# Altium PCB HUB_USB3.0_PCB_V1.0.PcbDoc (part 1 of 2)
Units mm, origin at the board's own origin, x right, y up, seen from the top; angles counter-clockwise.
Board outline 100 x 80 mm, 2 copper layers (Top Layer, Bottom Layer), stack 1.071 mm thick; 154 components, 104 nets, 521 pads, 700 vias.
Unrouted connection lines stored in the file: 114.
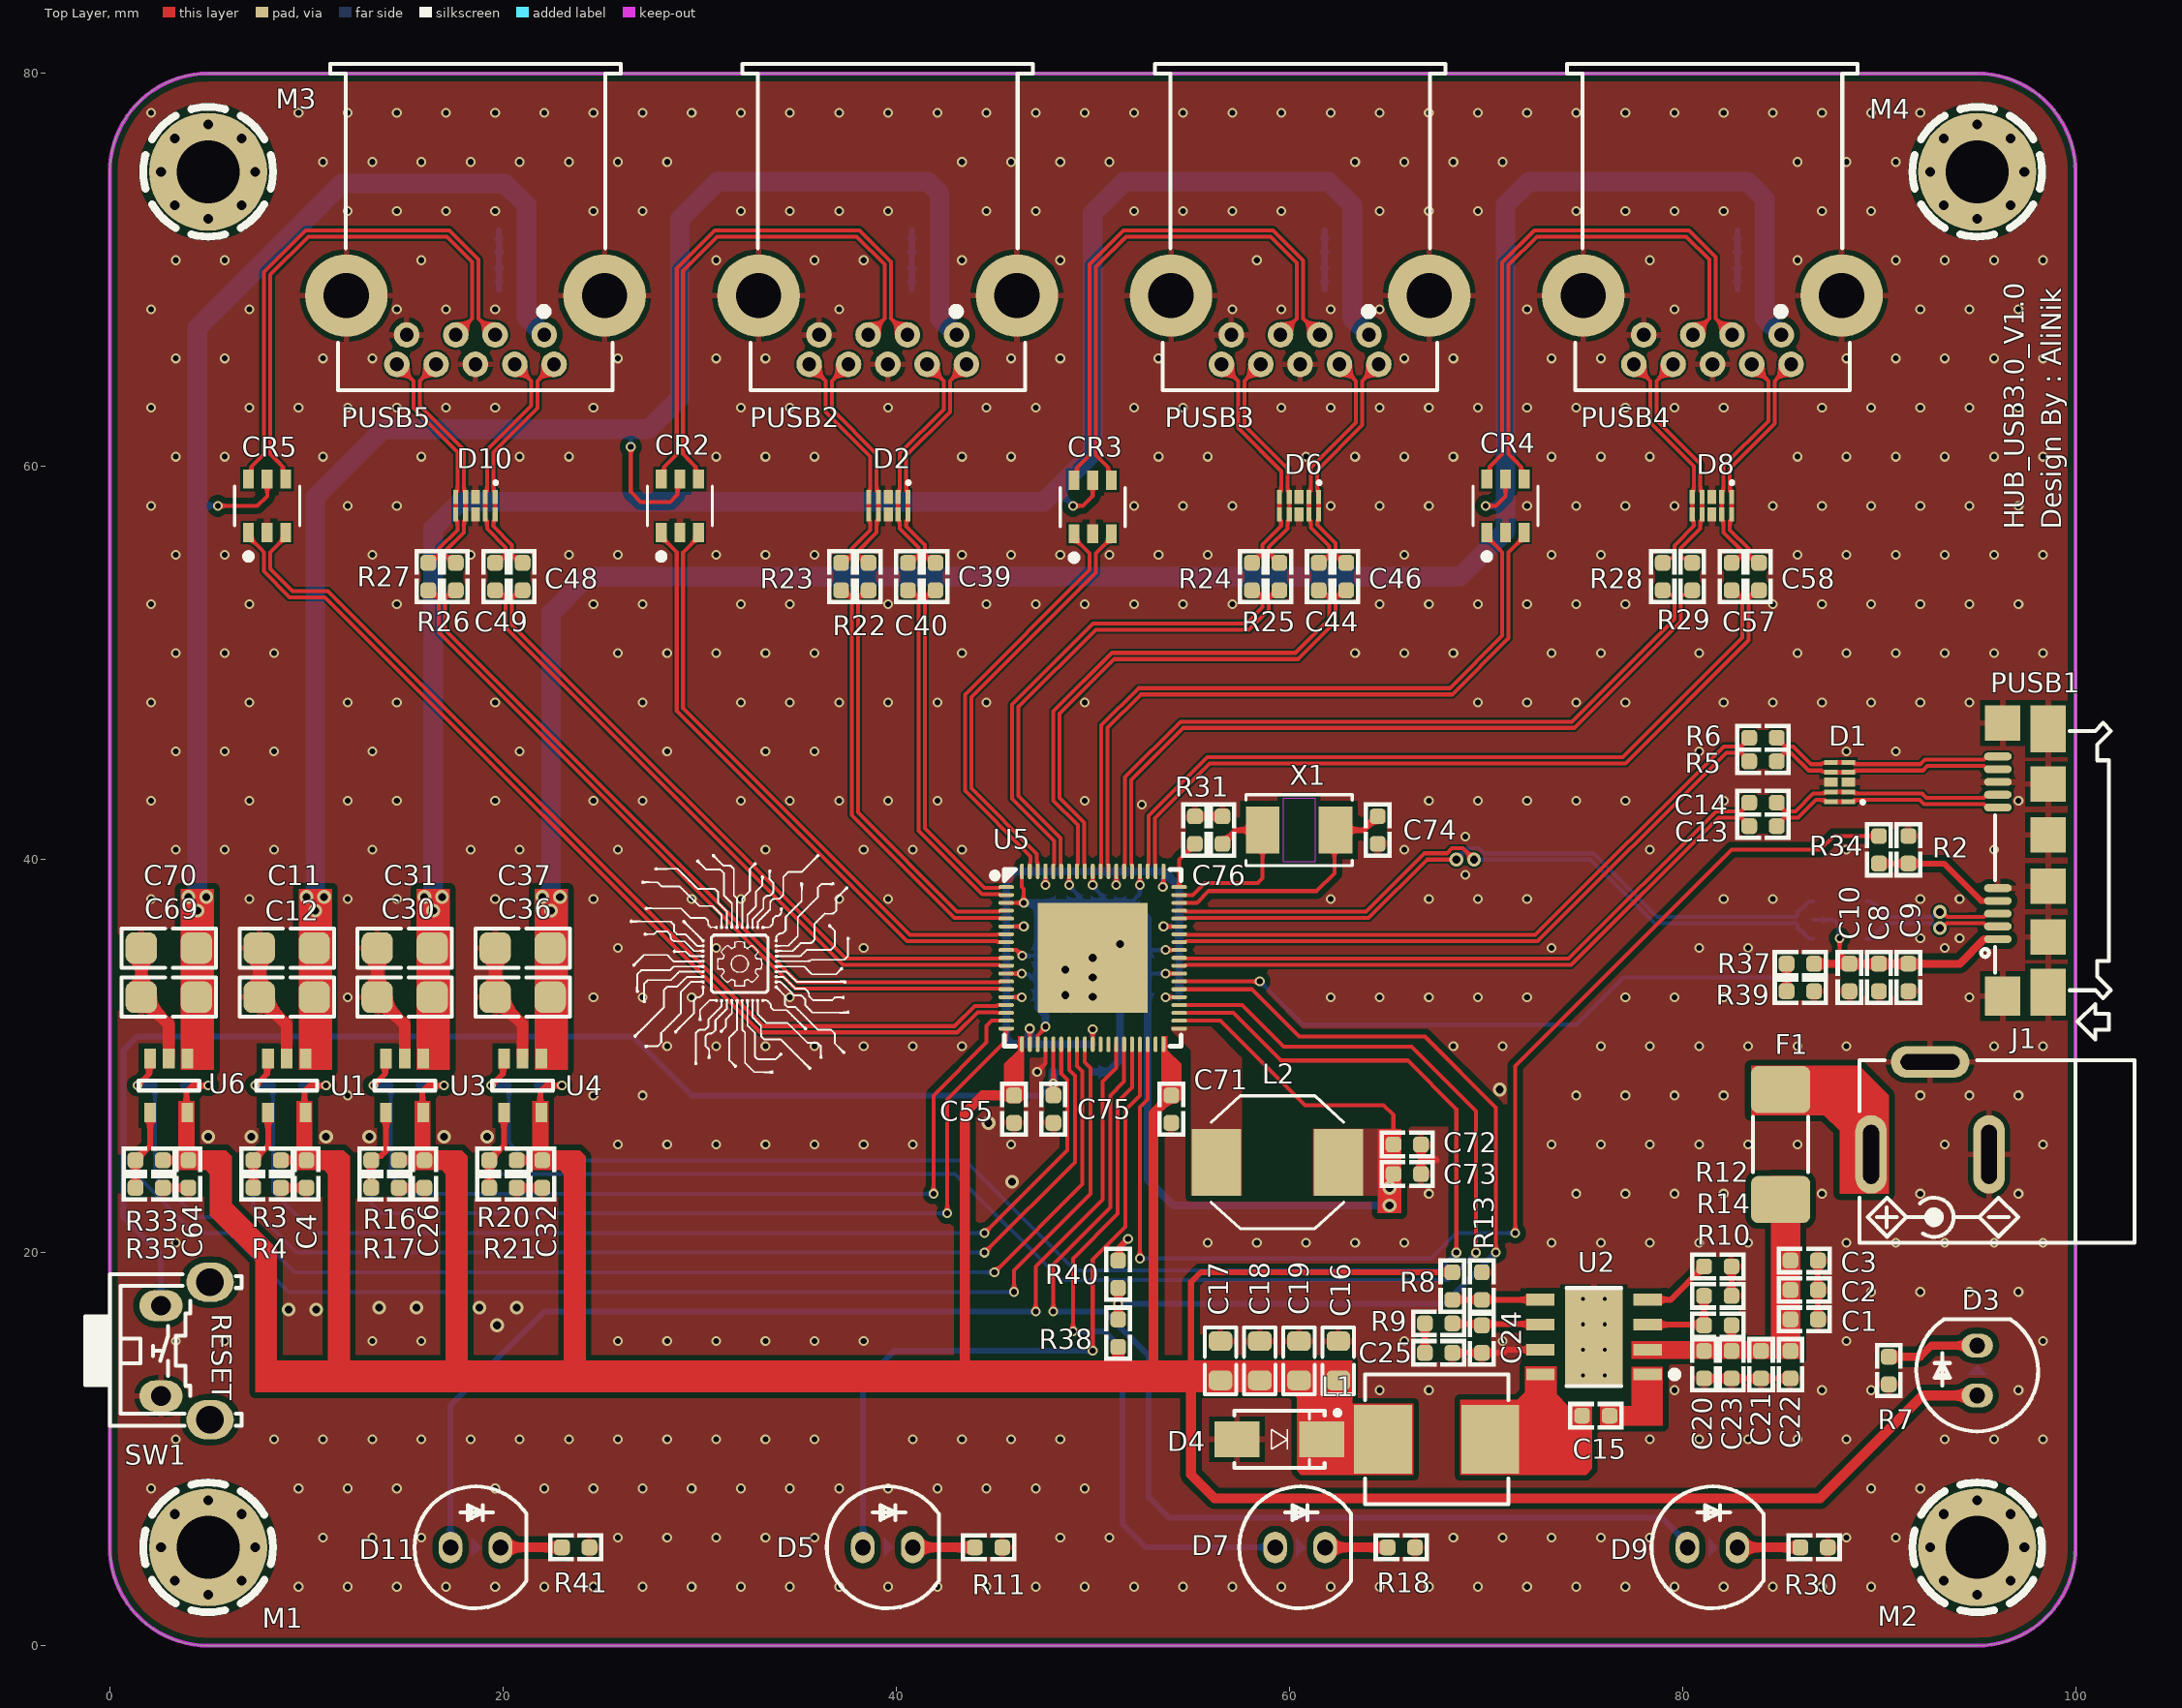
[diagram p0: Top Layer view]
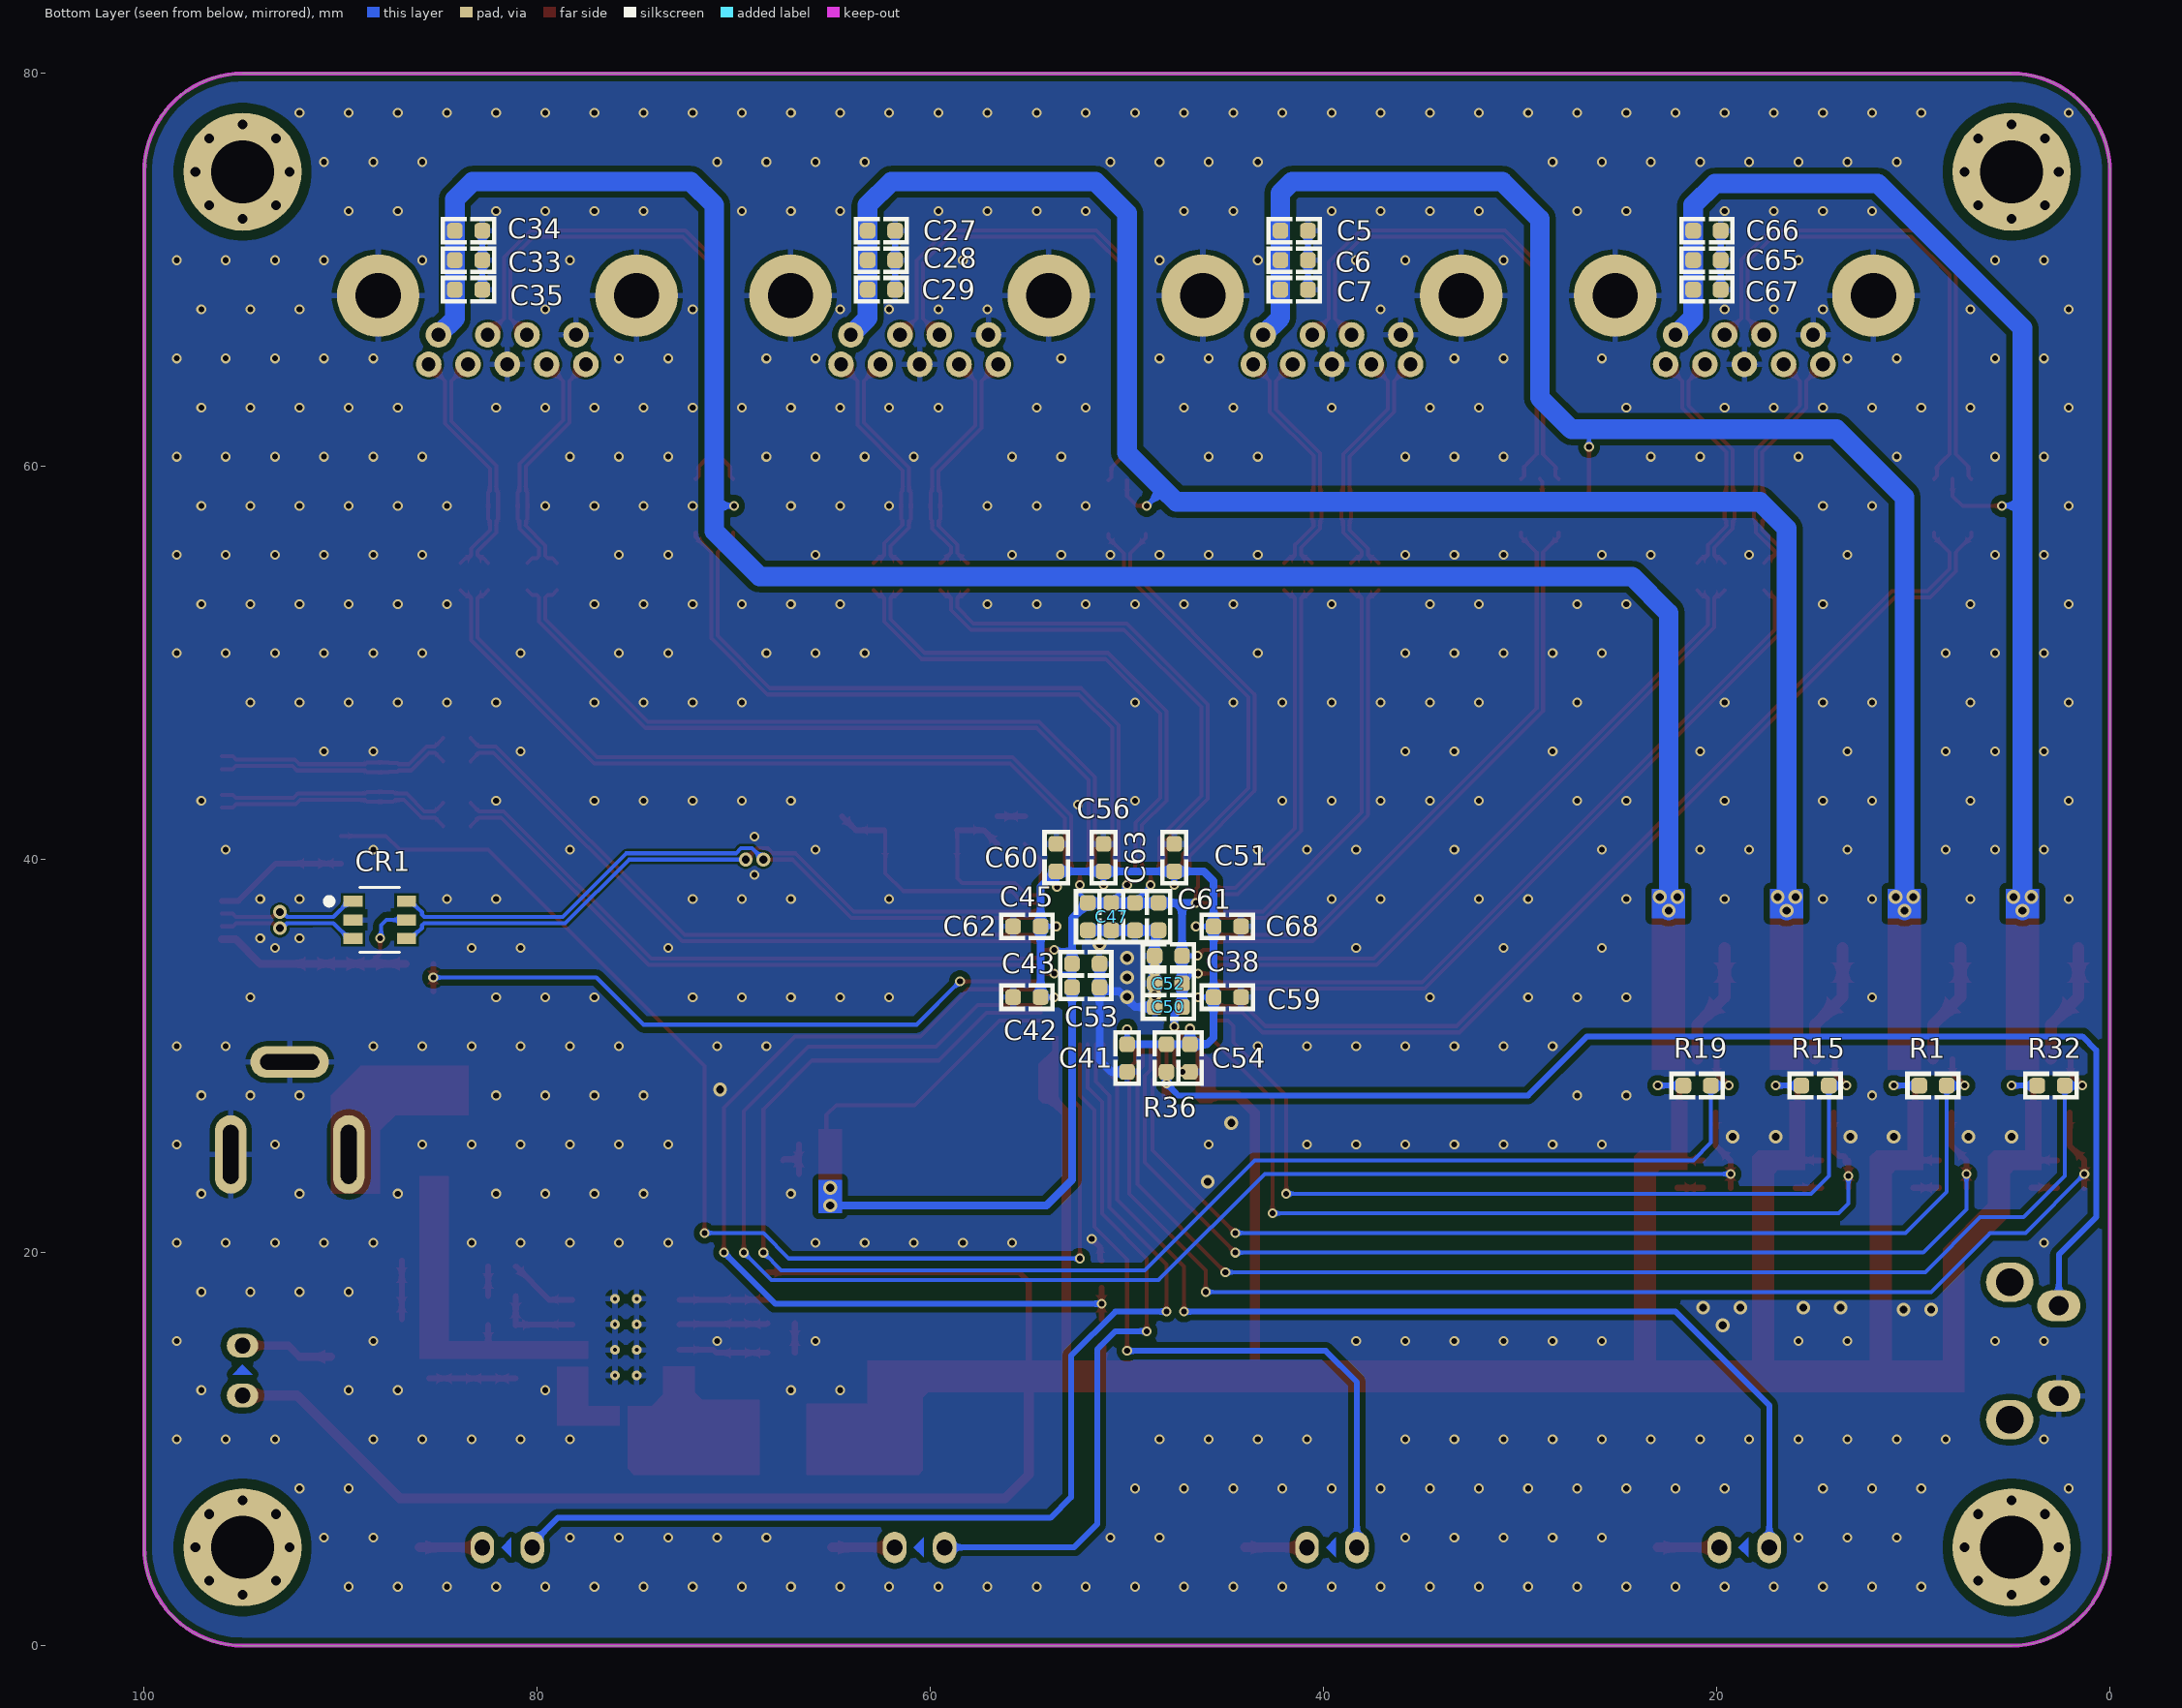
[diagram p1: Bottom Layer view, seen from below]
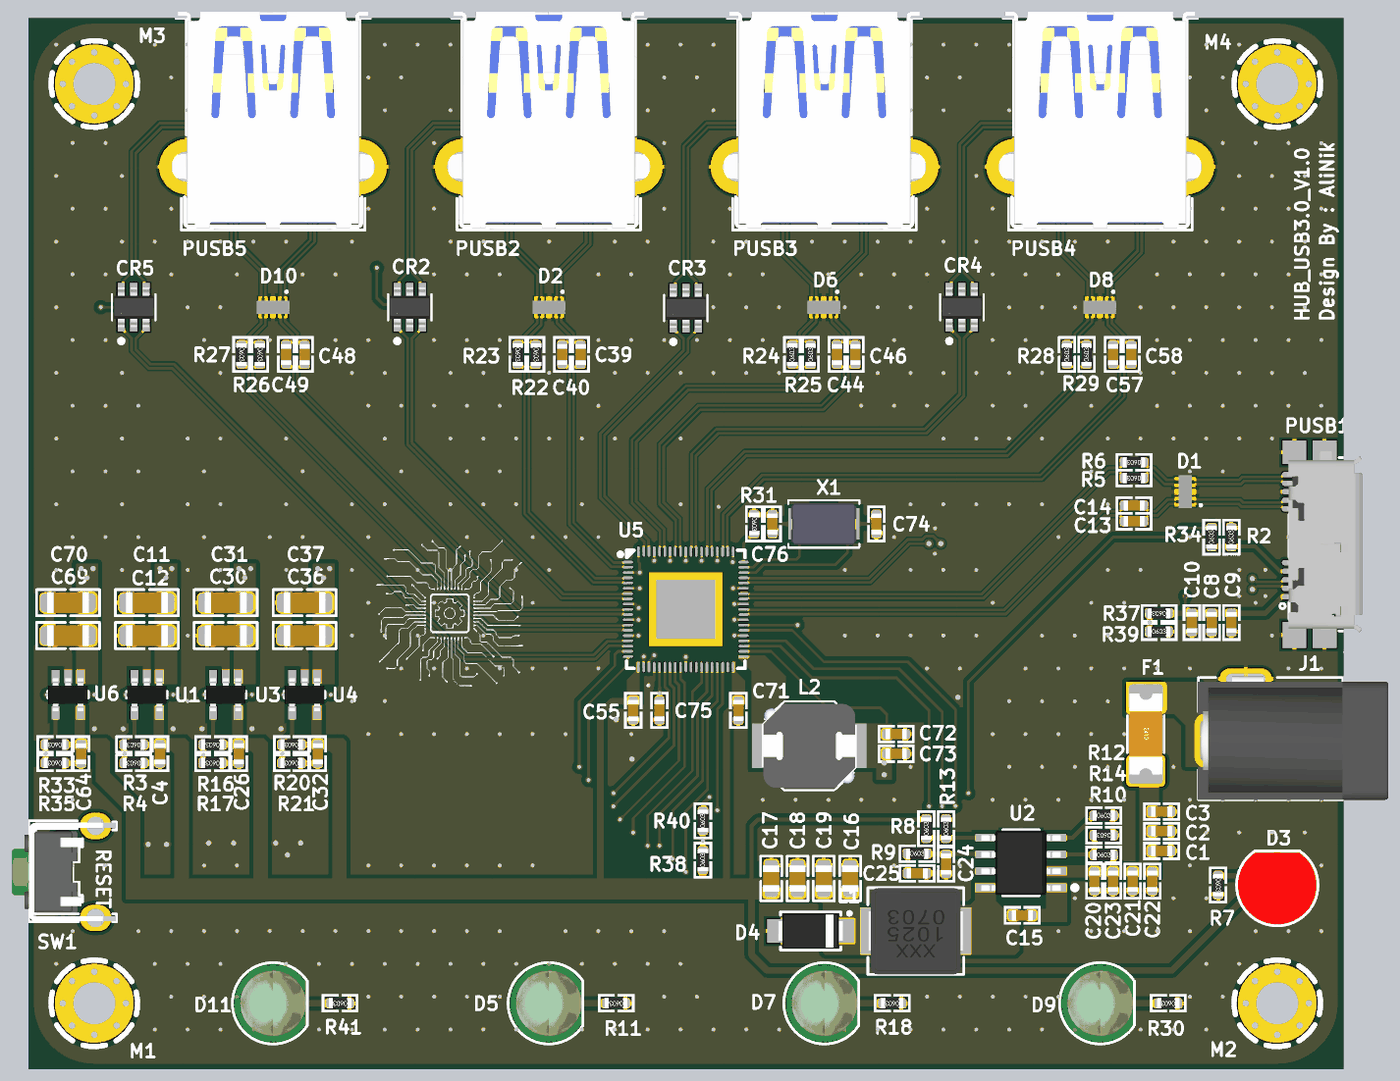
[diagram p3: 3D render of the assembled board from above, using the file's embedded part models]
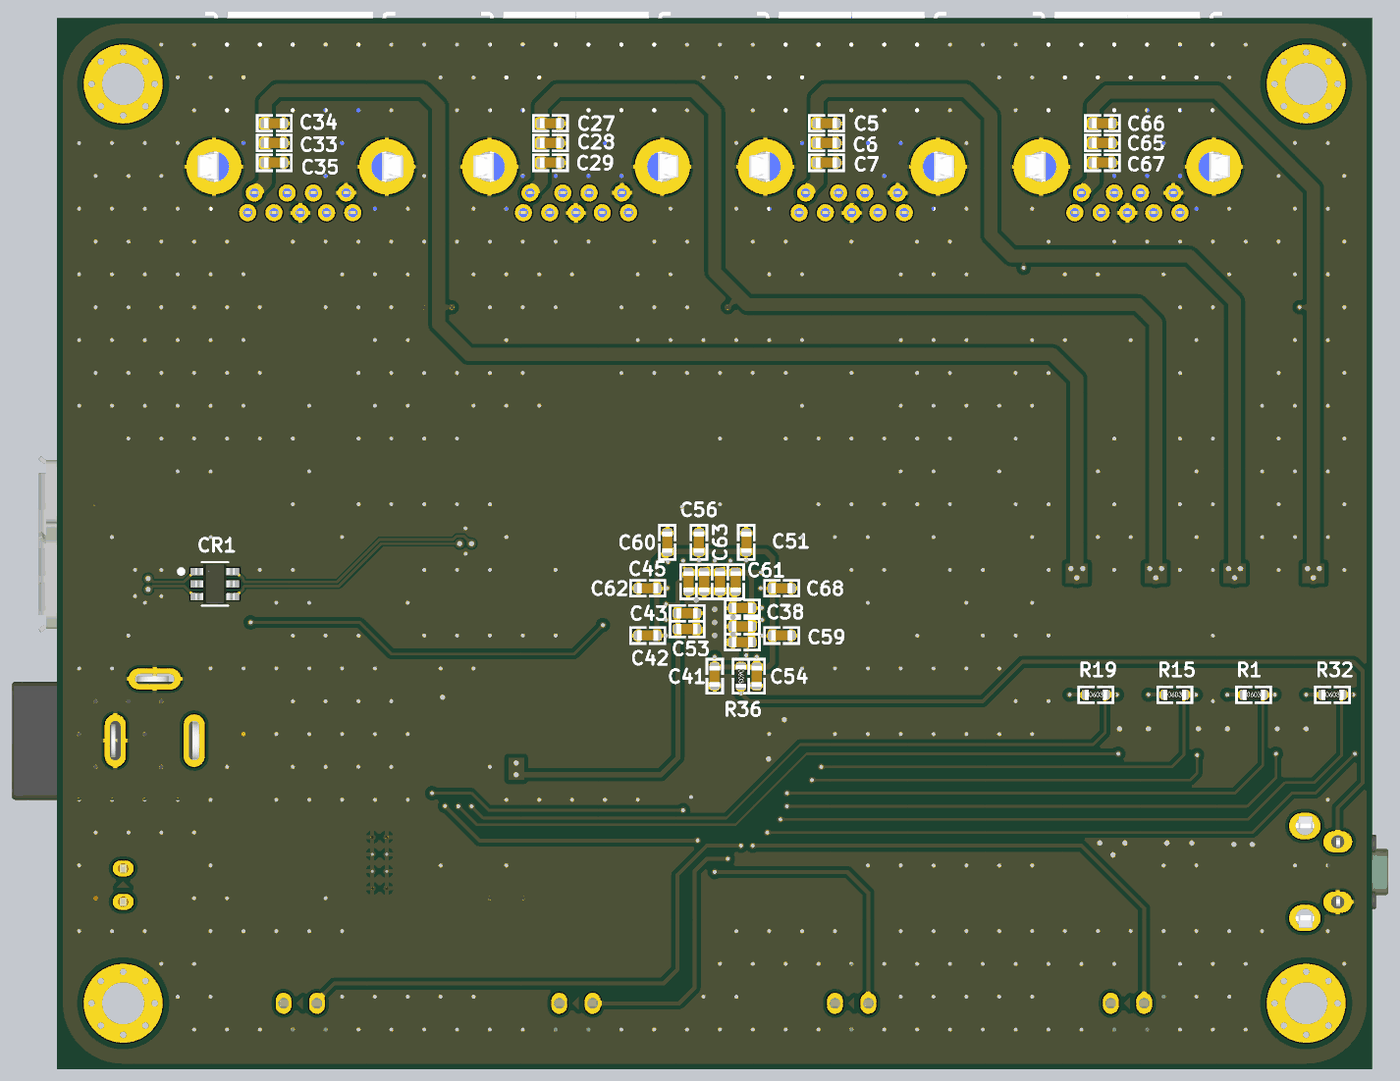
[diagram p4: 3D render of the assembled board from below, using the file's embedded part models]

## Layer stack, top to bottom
Top Solder: solder mask 0.0102, Solder Resist, Dk 3.5
Top Layer: signal copper 0.0356
Dielectric 1: dielectric 1, FR-4, Dk 4.8
Bottom Layer: signal copper 0.0356
Bottom Solder: solder mask 0.0102, Solder Resist, Dk 3.5

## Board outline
0,5 0,75 cw(c5,75) 5,80 95,80 cw(c95,75) 100,75 100,5 cw(c95,5) 95,0 5,0 cw(c5,5)

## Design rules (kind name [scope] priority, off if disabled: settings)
Clearance Clearance_USB [InNetClass('USB2.0') or InNetClass('USB3.0') vs InNetClass('USB2.0') or InNetClass('USB3.0') or InNet('GND')] p1: gap=0.12 ignorepadtopadclearanceinfootprint=FALSE
Clearance Clearance_Polygon [InPolygon and InNet('GND')] p2: gap=0.3 ignorepadtopadclearanceinfootprint=TRUE
Clearance [All] p3: gap=0.18 ignorepadtopadclearanceinfootprint=TRUE
DiffPairsRouting [All] p1: maxlimit=0.12 minlimit=0.12 mostfreqgap=0.12 toplayer_minwidth=0.2 toplayer_maxwidth=0.2 toplayer_prefwidth=0.2 bottomlayer_minwidth=0.2 bottomlayer_maxwidth=0.2 bottomlayer_prefwidth=0.2 impedanceprofiledriven=TRUE impedanceprofileid={F587BD4B-BCB3-41A8-9E42-C4C83C8BF323} impedanceprofilevalue=90.000000 maxuncoupledlength=12.7
HoleSize [All] p1: absolutevalues=TRUE maxlimit=5 minlimit=0.025 maxpercent=80.000 minpercent=20.000
MinimumSolderMaskSliver [All] p1: minsoldermaskwidth=0.15
PolygonConnect PolygonConnect_GND [InNet('GND')] p1: thpad.connectstyle=Relief thpad.reliefconductorwidth=0.3 thpad.reliefentries=4 thpad.polygonreliefangle="90 Angle" thpad.airgapwidth=0.25 smdpad.connectstyle=Relief smdpad.reliefconductorwidth=0.3 smdpad.reliefentries=4 smdpad.polygonreliefangle="90 Angle" smdpad.airgapwidth=0.25 via.connectstyle=Direct via.reliefconductorwidth=0.254 via.reliefentries=4 via.polygonreliefangle="90 Angle" via.airgapwidth=0.254
PolygonConnect [All] p2: connectstyle=Direct reliefconductorwidth=0.254 reliefentries=4 polygonreliefangle="90 Angle" airgapwidth=0.254
RoutingVias [All] p1: holewidth=0.3 width=0.5 viastyle="Through Hole" minholewidth=0.3 minwidth=0.5 maxholewidth=0.7 maxwidth=1.2
SilkToSilkClearance [All] p1: silktosilkclearance=0.15
SilkToSolderMaskClearance [IsPad] p1: minsilkscreentomaskgap=0.15 clearancetoexposedcopper=TRUE
SolderMaskExpansion [All] p1: expansion=0.102 istentingtop=FALSE
SupplyNets "Schematic Supply Nets_2" [InNet('VIN')] p1: voltage=0.000
SupplyNets "Schematic Supply Nets_11" [InNet('3.3V')] p2: voltage=0.000
SupplyNets "Schematic Supply Nets_10" [InNet('VBUS_Port4')] p3: voltage=0.000
SupplyNets "Schematic Supply Nets_9" [InNet('1.1V')] p4: voltage=0.000
SupplyNets "Schematic Supply Nets_8" [InNet('VBUS_Port2')] p5: voltage=0.000
SupplyNets "Schematic Supply Nets_6" [InNet('VBUS_Port1')] p6: voltage=0.000
SupplyNets "Schematic Supply Nets_5" [InNet('VBUS_Port3')] p7: voltage=0.000
SupplyNets "Schematic Supply Nets_4" [InNet('VBUS')] p8: voltage=0.000
SupplyNets "Schematic Supply Nets_3" [InNet('GND')] p9: voltage=0.000
SupplyNets "Schematic Supply Nets_1" [InNet('VCC')] p10: voltage=0.000
SupplyNets "Schematic Supply Nets" [InNet('5V')] p11: voltage=0.000
Width [All] p1: maxlimit=5 minlimit=0.15 preferedwidth=0.254
25 further rules are at their usual default settings.

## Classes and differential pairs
net class USB3.0: MAIN_SSRX_N MAIN_SSRX_P MAIN_SSTX_N MAIN_SSTX_P RX0_N RX0_P RX1_N RX1_P RX2_N RX2_P RX3_N RX3_P RX4_N RX4_P SSRX1_N SSRX1_P SSRX2_N SSRX2_P SSRX3_N SSRX3_P SSRX4_N SSRX4_P SSTX1_N SSTX1_P SSTX2_N SSTX2_P SSTX3_N SSTX3_P SSTX4_N SSTX4_P TX0_N TX0_P TX1_N TX1_P TX2_N TX2_P TX3_N TX3_P TX4_N TX4_P
net class USB2.0: D0_N D0_P D1_N D1_P D2_N D2_P D3_N D3_P D4_N D4_P HSD1_N HSD1_P HSD2_N HSD2_P HSD3_N HSD3_P HSD4_N HSD4_P MAIN_D_N MAIN_D_P
differential pair D0: +MAIN_D_P -MAIN_D_N
differential pair TX4: +TX4_P -TX4_N
differential pair TX3: +TX3_P -TX3_N
differential pair TX2: +TX2_P -TX2_N
differential pair TX1: +TX1_P -TX1_N
differential pair TX0: +TX0_P -TX0_N
differential pair SSTX4: +SSTX4_P -SSTX4_N
differential pair SSTX3: +SSTX3_P -SSTX3_N
differential pair SSTX2: +SSTX2_P -SSTX2_N
differential pair SSTX1: +SSTX1_P -SSTX1_N
differential pair SSRX4: +SSRX4_P -SSRX4_N
differential pair SSRX3: +SSRX3_P -SSRX3_N
differential pair SSRX2: +SSRX2_P -SSRX2_N
differential pair SSRX1: +SSRX1_P -SSRX1_N
differential pair RX4: +RX4_P -RX4_N
differential pair RX3: +RX3_P -RX3_N
differential pair RX2: +RX2_P -RX2_N
differential pair RX1: +RX1_P -RX1_N
differential pair RX0: +RX0_P -RX0_N
differential pair HSD4: +HSD4_P -HSD4_N
differential pair HSD3: +HSD3_P -HSD3_N
differential pair HSD2: +HSD2_P -HSD2_N
differential pair HSD1: +HSD1_P -HSD1_N
differential pair D4: +D4_P -D4_N
differential pair D3: +D3_P -D3_N
differential pair D2: +D2_P -D2_N
differential pair D1: +D1_P -D1_N
differential pair MAIN_SSTX: +MAIN_SSTX_P -MAIN_SSTX_N
differential pair MAIN_SSRX: +MAIN_SSRX_P -MAIN_SSRX_N
differential pair MAIN_D: +D0_P -D0_N

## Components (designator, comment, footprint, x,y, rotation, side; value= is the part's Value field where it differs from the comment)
C1 "10uF" C0603 86.2,16.6 r0 top
C2 "10uF" C0603 86.2,18.1 r0 top
C3 "100nF" C0603 86.2,19.6 r0 top
C4 "100nF" C0603 10,24 r90 top
C5 "10uF" C0603 41.5,72 r180 bottom
C6 "10uF" C0603 41.5,70.5 r180 bottom
C7 "100nF" C0603 41.5,69 r180 bottom
C8 "10uF" C0603 90,34 r270 top
C9 "10uF" C0603 91.5,34 r270 top
C10 "100nF" C0603 88.5,34 r270 top
C11 "100uF" C1206 9,35.5 r0 top
C12 "100uF" C1206 9,33 r0 top
C13 "100nF" C0603 84.1,41.7 r180 top
C14 "100nF" C0603 84.1,42.9 r180 top
C15 "100nF" C0603 75.6,11.7 r0 top
C16 "47uF" C0805 62.5,14.5 r270 top
C17 "47uF" C0805 56.5,14.5 r270 top
C18 "47uF" C0805 58.5,14.5 r270 top
C19 "47uF" C0805 60.5,14.5 r270 top
C20 "2.2uF" C0603 81.1,14.3 r90 top
C21 "2.2uF" C0603 84,14.3 r90 top
C22 "2.2uF" C0603 85.5,14.3 r90 top
C23 "2.2uF" C0603 82.5,14.3 r90 top
C24 "47pF" C0603 69.8,15.6 r270 top
C25 "4.7nF" C0603 67.6,14.9 r0 top
C26 "100nF" C0603 16,24 r90 top
C27 "10uF" C0603 62.5,72 r180 bottom
C28 "10uF" C0603 62.5,70.5 r180 bottom
C29 "100nF" C0603 62.5,69 r180 bottom
C30 "100uF" C1206 15,33 r0 top
C31 "100uF" C1206 15,35.5 r0 top
C32 "100nF" C0603 22,24 r90 top
C33 "10uF" C0603 83.5,70.5 r180 bottom
C34 "10uF" C0603 83.5,72 r180 bottom
C35 "100nF" C0603 83.5,69 r180 bottom
C36 "100uF" C1206 21,33 r0 top
C37 "100uF" C1206 21,35.5 r0 top
C38 "100nF" C0603 47.9,35.1 r180 bottom
C39 "100nF" C0603 42,54.4 r270 top
C40 "100nF" C0603 40.6,54.4 r270 top
C41 "100nF" C0603 50,29.9 r90 bottom
C42 "100nF" C0603 55.1,33 r180 bottom
C43 "100nF" C0603 52.1,34.7 r0 bottom
C44 "100nF" C0603 61.5,54.4 r90 top
C45 "100nF" C0603 52,37.1 r90 bottom
C46 "100nF" C0603 62.9,54.4 r90 top
C47 "100nF" C0603 50.8,37.1 r90 bottom
C48 "100nF" C0603 21,54.4 r270 top
C49 "100nF" C0603 19.6,54.4 r270 top
C50 "100nF" C0603 47.9,32.5 r180 bottom
C51 "100nF" C0603 47.6,40.1 r270 bottom
C52 "100nF" C0603 47.9,33.7 r180 bottom
C53 "100nF" C0603 52.1,33.5 r0 bottom
C54 "4.7uF" C0603 46.8,29.9 r90 bottom
C55 "10uF" C0603 46,27.3 r90 top
C56 "100nF" C0603 51.2,40.1 r270 bottom
C57 "100nF" C0603 82.5,54.4 r90 top
C58 "100nF" C0603 83.9,54.4 r90 top
C59 "100nF" C0603 44.9,33 r0 bottom
C60 "100nF" C0603 53.6,40.1 r270 bottom
C61 "100nF" C0603 48.4,37.1 r90 bottom
C62 "100nF" C0603 55.1,36.6 r180 bottom
C63 "100nF" C0603 49.6,37.1 r90 bottom
C64 "100nF" C0603 4,24 r90 top
C65 "10uF" C0603 20.5,70.5 r180 bottom
C66 "10uF" C0603 20.5,72 r180 bottom
C67 "100nF" C0603 20.5,69 r180 bottom
C68 "100nF" C0603 44.9,36.6 r0 bottom
C69 "100uF" C1206 3,33 r0 top
C70 "100uF" C1206 3,35.5 r0 top
C71 "10uF" C0603 54,27.3 r270 top
C72 "10uF" C0603 66,25.5 r0 top
C73 "10uF" C0603 66,24 r0 top
C74 "15pF" C0603 64.5,41.5 r270 top
C75 "100nF" C0603 48,27.3 r90 top
C76 "15pF" C0603 56.6,41.5 r90 top
CR1 "USBLC6-4SC6" SOT23-6L_STM 88.018,36.928 r180 bottom
CR2 "USBLC6-4SC6" SOT23-6L_STM 29,58 r90 top
CR3 "USBLC6-4SC6" SOT23-6L_STM 50,57.938 r90 top
CR4 "USBLC6-4SC6" SOT23-6L_STM 71,58 r90 top
CR5 "USBLC6-4SC6" SOT23-6L_STM 8,58 r90 top
D1 "SEUC10F5V4U-MS" UDFN10_DTS 88,43.943 r180 top
D2 "SEUC10F5V4U-MS" UDFN10_DTS 39.6,58 r270 top
D3 "LED5MM_RED" LED5MM_RED 95,14 r90 top
D4 "SS56" DO-214AC 59.5,10.5 r0 top
D5 "LED5MM_GRN" LED5MM_GRN 39.577,5 r0 top
D6 "SEUC10F5V4U-MS" UDFN10_DTS 60.5,58 r270 top
D7 "LED5MM_GRN" LED5MM_GRN 60.553,5 r0 top
D8 "SEUC10F5V4U-MS" UDFN10_DTS 81.5,58 r270 top
D9 "LED5MM_GRN" LED5MM_GRN 81.53,5 r0 top
D10 "SEUC10F5V4U-MS" UDFN10_DTS 18.6,58 r270 top
D11 "LED5MM_GRN" LED5MM_GRN 18.6,5 r0 top
F1 "FUSE2A" F2410 85,25.5 r270 top
J1 "DC_POWER_JACK" JAC_PWR2 89.6,25 r270 top
L1 "TMPC0603H-8R2MG-D" IND_7.3x6.6mm 67.5,10.5 r180 top value=8.2uH
L2 "SPM6530T-4R7M" IND_SPM6530_TDK 59.4,24.6 r0 top value=4.7uH
M1 "DNP/MH" SCMH_M3 5,5 r0 top
M2 "DNP/MH" SCMH_M3 95,5 r0 top
M3 "DNP/MH" SCMH_M3 5,75 r0 top
M4 "DNP/MH" SCMH_M3 95,75 r0 top
PUSB1 "CONN_USB3" USB3_MICRO_B 97.2,40 r270 top
PUSB2 "CONN_USB3_A" USB3_A_RA 39.577,68.7 r0 top
PUSB3 "CONN_USB3_A" USB3_A_RA 60.553,68.7 r0 top
PUSB4 "CONN_USB3_A" USB3_A_RA 81.53,68.7 r0 top
PUSB5 "CONN_USB3_A" USB3_A_RA 18.6,68.7 r0 top
R1 "10K" R0603 9,28.5 r180 bottom
R2 "5.1K" R0603 91.5,40.5 r90 top
R3 "NA" R0603 8,24.7 r180 top
R4 "NA" R0603 8,23.3 r180 top
R5 "0R" R0603 84.1,45 r180 top
R6 "0R" R0603 84.1,46.2 r180 top
R7 "3.3K" R0603 90.5,14 r270 top
R8 "56K" R0603 68.3,18.3 r90 top
R9 "16.9K" R0603 67.6,16.4 r0 top
R10 "12K" R0603 81.8,16.3 r0 top
R11 "2.2K" R0603 44.7,5 r180 top
R12 "243K" R0603 81.8,19.3 r0 top
R13 "10K" R0603 69.8,18.3 r90 top
R14 "68K" R0603 81.8,17.8 r180 top
R15 "10K" R0603 15,28.5 r180 bottom
R16 "NA" R0603 14,24.7 r180 top
R17 "NA" R0603 14,23.3 r180 top
R18 "2.2K" R0603 65.7,5 r180 top
R19 "10K" R0603 21,28.5 r180 bottom
R20 "NA" R0603 20,24.7 r180 top
R21 "NA" R0603 20,23.3 r180 top
R22 "0R" R0603 38.6,54.4 r270 top
R23 "0R" R0603 37.2,54.4 r270 top
R24 "0R" R0603 58.1,54.4 r90 top
R25 "0R" R0603 59.5,54.4 r90 top
R26 "0R" R0603 17.6,54.4 r270 top
R27 "0R" R0603 16.2,54.4 r270 top
R28 "0R" R0603 79,54.4 r90 top
R29 "0R" R0603 80.5,54.4 r90 top
R30 "2.2K" R0603 86.7,5 r180 top
R31 "6.04K" R0603 55.2,41.5 r270 top
R32 "10K" R0603 3,28.5 r180 bottom
R33 "NA" R0603 2,24.7 r180 top
R34 "NA" R0603 90,40.5 r90 top
R35 "NA" R0603 2,23.3 r180 top
R36 "10K" R0603 48,29.9 r270 bottom
R37 "4.7K" R0603 86,34.7 r180 top
R38 "4.7K" R0603 51.3,15.9 r90 top
R39 "10K" R0603 86,33.3 r0 top
R40 "10K" R0603 51.3,18.9 r90 top
R41 "2.2K" R0603 23.7,5 r180 top
SW1 "PUSHBUTTON" SWPBT_SPST_R_6X6X4 2.6,15 r90 top
U1 "TPS2065DDBVR" DBV0005A_N 9,28.5 r270 top
U2 "TPS54560DDA" DDA0008E_N 75.5,15.7 r180 top
U3 "TPS2065DDBVR" DBV0005A_N 15,28.5 r270 top
U4 "TPS2065DDBVR" DBV0005A_N 21,28.5 r270 top
U5 "VL817-Q7(B0)" QFN-76_L9.0-W9.0-P0.40-BL-EP 50,35 r270 top
U6 "TPS2065DDBVR" DBV0005A_N 3,28.5 r270 top
X1 "7A-25.000MAAJ-T" CRYSTAL_TXC_7A_TXC 60.5,41.5 r0 top

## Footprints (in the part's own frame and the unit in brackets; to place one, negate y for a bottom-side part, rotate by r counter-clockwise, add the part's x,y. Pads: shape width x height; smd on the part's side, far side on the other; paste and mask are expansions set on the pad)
C0603 [mm] "CHIP Capacitor, 1.6X0.8mm, 0603 OPTIMIZED"
  rrect50% 0.8x0.8 smd paste-5 mask+0.075: 1(-0.7,0) 2(0.7,0)
  Top Layer pour cut-out: -0.5,0.4 0.5,0.4 0.5,-0.4 -0.5,-0.4
  silkscreen extent -1.4,-0.7 1.4,0.7, body extent -0.8,-0.4 0.8,0.4, height 0.9
C0805 [mm] "CHIP Capacitor, 2.0X1.3mm, 0805"
  rrect50% 1x1.2 smd paste-0.1 mask+0.075: 1(-1,0) 2(1,0)
  Top Layer pour cut-out: -0.5,0.8 0.5,0.8 0.5,-0.8 -0.5,-0.8
  silkscreen extent -1.7,-0.8 1.7,0.8, body extent -1,-0.62 1,0.63, height 1
C1206 [mm] "CHIP Capacitor, 3.2X1.6mm, 1206"
  rrect50% 1.6x1.6 smd paste-0.8 mask+0.075: 1(-1.4,0) 2(1.4,0)
  Top Layer pour cut-out: -0.8,1 -0.8,-1 0.8,-1 0.8,1
  silkscreen extent -2.4,-1 2.4,1, body extent -1.6,-0.8 1.6,0.8, height 1
CRYSTAL_TXC_7A_TXC [mil]
  rect 67x94 smd paste+0 mask+0: 1(-73,0) 2(73,0)
  Top Layer keep-out region: -31.5,-64 -31.5,64 31.5,64 31.5,-64
  silkscreen extent -107,-71 107,71, body extent -98,-63 98,63, height 51
DBV0005A_N [mm]
  rect 1x0.6 smd paste+0 mask+0.051: 1(-1.375,0.95) 2(-1.375,0) 3(-1.375,-0.95) 4(1.375,-0.95) 5(1.375,0.95)
  silkscreen extent -0.25,-1.55 0.25,1.55, body extent -1.25,-1.5 1.25,1.5, height 1.06
DDA0008E_N [mm]
  rect 1.45x0.6 smd paste+0 mask+0.05: 1(-2.725,1.905) 2(-2.725,0.635) 3(-2.725,-0.635) 4(-2.725,-1.905) 5(2.725,-1.905) 6(2.725,-0.635) 7(2.725,0.635) 8(2.725,1.905)
  rect 2.95x4.9 smd paste-2.437 mask-2.438: 9(0,0)
  round 0.5 hole 0.203 paste-2539.97 mask-0.241: V(-0.55,1.95) V(-0.55,0.65) V(-0.55,-0.65) V(-0.55,-1.95) V(0.55,1.95) V(0.55,0.65) V(0.55,-0.65) V(0.55,-1.95)
  silkscreen extent -4.2,-2.5 1.4,2.5, body extent -3.01,-2.45 3.01,2.45, height 1.7
DO-214AC [mm]
  rect 2.3x1.8 smd: 1(-2.159,0) 2(2.159,0)
  silkscreen extent -2.3,-1.45 3.08,1.47, body extent -2.5,-1.35 2.5,1.35, height 2.2
F2410 [mm] "FUSE, 6x2.5mm"
  rrect30% 2.4x3 smd paste-0.2 mask+0.1: 1(-2.8,0) 2(2.8,0)
  silkscreen extent -1.4,-1.4 1.4,1.4, body extent -3.09,-1.25 3.09,1.25, height 2.18
IND_7.3x6.6mm [mm]
  rect 2.95x3.5 smd mask+0.05: 1(-2.725,0) 2(2.725,0)
  silkscreen extent -3.65,-3.3 3.65,3.3, body extent -3.65,-3.3 3.65,3.3, height 3
IND_SPM6530_TDK [mm]
  rect 2.5x3.4 smd paste+0 mask+0: 1(-3.1,0) 2(3.1,0)
  silkscreen extent -3.37,-3.38 3.37,3.38, body extent -3.6,-3.2 3.6,3.2, height 3.1
JAC_PWR2 [mm] "DC POWER JACK, Power Jack KLDX-0202"
  oval 4x1.6 hole 0.8 slot 3 at 0 deg: 1(0,0) 2(0,6)
  oval 1.6x4 hole 0.8 slot 3 at 90 deg: 3(-4.7,3)
  silkscreen extent -4.8,-0.6 4.5,13.4, body extent -4.9,-0.65 4.5,13.85, height 10.8
LED5MM_GRN [mm] "LED THD 5MM GREEN"
  oval 1.2x1.6 hole 0.8: 1(-1.27,0) 2(1.27,0)
  Bottom Layer region: -0.2,0.5 -0.2,-0.5 0.3,0
  silkscreen extent -3.1,-3.1 2.6,3.1, body extent -3,-3 2.5,3, height 9.14
LED5MM_RED [mm] "LED THD 5MM RED"
  oval 1.2x1.6 hole 0.8: 1(-1.27,0) 2(1.27,0)
  Bottom Layer region: -0.2,0.5 -0.2,-0.5 0.3,0
  silkscreen extent -3.1,-3.1 2.6,3.1, body extent -3,-3 2.5,3, height 9.14
QFN-76_L9.0-W9.0-P0.40-BL-EP [mil]
  oval 7.9x31.5 smd paste-3937 mask+2: 1(-141.7,-173.2) 2(-125.9,-173.2) 3(-110.2,-173.2) 4(-94.4,-173.2) 5(-78.7,-173.2) 6(-62.9,-173.2) 7(-47.2,-173.2) 8(-31.5,-173.2) 9(-15.7,-173.2) 10(0,-173.2) 11(15.8,-173.2) 12(31.5,-173.2) 13(47.3,-173.2) 14(63,-173.2) 15(78.8,-173.2) 16(94.5,-173.2) 17(110.3,-173.2) 18(126,-173.2) 19(141.8,-173.2) 39(141.8,173.2) 40(126,173.2) 41(110.3,173.2) 42(94.5,173.2) 43(78.8,173.2) 44(63,173.2) 45(47.3,173.2) 46(31.5,173.2) 47(15.8,173.2) 48(0,173.2) 49(-15.7,173.2) 50(-31.5,173.2) 51(-47.2,173.2) 52(-62.9,173.2) 53(-78.7,173.2) 54(-94.4,173.2) 55(-110.2,173.2) 56(-125.9,173.2) 57(-141.7,173.2)
  oval 31.5x7.9 smd paste-3937 mask+2: 20(173.2,-141.7) 21(173.2,-126) 22(173.2,-110.2) 23(173.2,-94.5) 24(173.2,-78.7) 25(173.2,-63) 26(173.2,-47.2) 27(173.2,-31.5) 28(173.2,-15.7) 29(173.2,0) 30(173.2,15.8) 31(173.2,31.5) 32(173.2,47.3) 33(173.2,63) 34(173.2,78.7) 35(173.2,94.5) 36(173.2,110.2) 37(173.2,126) 38(173.2,141.7) 58(-173.2,141.7) 59(-173.2,126) 60(-173.2,110.2) 61(-173.2,94.5) 62(-173.2,78.7) 63(-173.2,63) 64(-173.2,47.3) 65(-173.2,31.5) 66(-173.2,15.8) 67(-173.2,0) 68(-173.2,-15.7) 69(-173.2,-31.5) 70(-173.2,-47.2) 71(-173.2,-63) 72(-173.2,-78.7) 73(-173.2,-94.5) 74(-173.2,-110.2) 75(-173.2,-126) 76(-173.2,-141.7)
  rect 220.5x220.5 smd paste-3937 mask+2: 77(0,0)
  silkscreen extent -177,-202 177,177, body extent -171,-171 171,171, height 33
R0603 [mm] "CHIP Resistor 1/10 WATT, 1.6x0.8mm, 0603, OPTIMIZED"
  rrect50% 0.8x0.8 smd paste-5 mask+0.075: 1(-0.7,0) 2(0.7,0)
  Top Layer pour cut-out: -0.5,0.4 0.5,0.4 0.5,-0.4 -0.5,-0.4
  silkscreen extent -1.4,-0.7 1.4,0.7, body extent -0.85,-0.4 0.85,0.4, height 0.56
SCMH_M3 [mm] "SCREW mouting, M3, 3.0mm diameter and 6.0mm PanHead"
  round 6 / inner round 3.5 / far side round 6 hole 3.2 mask+0.1: 1(0,0)
  Top Layer pour cut-out: 0,3.5 -1.339,3.234 -2.475,2.475 -3.234,1.339 -3.5,0 -3.5,0 -3.234,-1.339 -2.475,-2.475 -1.339,-3.234 0,-3.5 0,-3.5 1.75,-3.031 3.031,-1.75 3.5,0 3.5,0 3.234,1.339 2.475,2.475 1.339,3.234 0,3.5
  Bottom Layer pour cut-out: 0,3.5 -1.339,3.234 -2.475,2.475 -3.234,1.339 -3.5,0 -3.5,0 -3.234,-1.339 -2.475,-2.475 -1.339,-3.234 0,-3.5 0,-3.5 1.75,-3.031 3.031,-1.75 3.5,0 3.5,0 3.234,1.339 2.475,2.475 1.339,3.234 0,3.5
  silkscreen extent -3.3,-3.3 3.3,3.3
SOT23-6L_STM [mm]
  rect 0.972x0.558 smd paste+0 mask+0.1: 1(-1.362,0.95) 2(-1.362,0) 3(-1.362,-0.95) 4(1.362,-0.95) 5(1.362,0) 6(1.362,0.95)
  silkscreen extent -2.7,-1.65 1,1.65, body extent -1.5,-1.52 1.5,1.52, height 1.45
SWPBT_SPST_R_6X6X4 [mm] "SWITCH, PUSHBUTTON, THD, SPST, 6X6X3.85 mm; 1,000,000 cycles ; 0.98N Force, SKHHLMA010"
  oval 1.6x2.2 hole 1 mask+0.1: 1(-2.3,0) 2(2.3,0)
  oval 2x2.4 hole 1.4 mask+0.1: ""(-3.5,-2.5) ""(3.5,-2.5)
  silkscreen extent -3.8,-4.1 3.9,3.85, body extent -4.25,-4.04 4.25,3.86, height 7.43
UDFN10_DTS [mil]
  rect 28x10 smd paste-14 mask+1.97: 1(-17.5,39.37) 2(-17.5,19.68) 4(-17.5,-19.68) 5(-17.5,-39.37) 6(17.5,-39.37) 7(17.5,-19.68) 9(17.5,19.68) 10(17.5,39.37)
  rect 28x18 smd paste-14 mask+1.97: 3(-17.5,0) 8(17.5,0)
  silkscreen extent -49,38 -44,43, body extent -20,-49 20,49, height 18
USB3_A_RA [mm] "USB 3.0 Receptecal, Type A, Top Mount, Through Hole, Horizontal"
  round 1.3 hole 0.7: 1(3.5,-2) 2(1,-2) 3(-1,-2) 4(-3.5,-2) 5(-4,-3.5) 6(-2,-3.5) 7(0,-3.5) 8(2,-3.5) 9(4,-3.5)
  round 4.2 hole 2.3: SH1(-6.57,0) SH2(6.57,0)
  silkscreen extent -7.39,-4.83 7.39,11.79, body extent -7.8,-4.8 7.8,11.8, height 7.77
USB3_MICRO_B [mm] "CONN, USB3, Micro B, CMS1811-010010 (HOSIDEN), GSB343133HR (AMPHENOL)"
  oval 0.4x1.4 smd: 1(4.05,-1.15) 2(3.4,-1.15) 3(2.75,-1.15) 4(2.1,-1.15) 5(1.45,-1.15) 6(-2.65,-1.15) 7(-3.3,-1.15) 8(-3.95,-1.15) 9(-4.6,-1.15) 10(-5.25,-1.15)
  rect 1.8x1.8 smd: SH1(-6.95,-0.9) SH3(-3.85,1.4) SH4(-1.25,1.4) SH5(1.35,1.4) SH6(3.95,1.4)
  rect 2.4x1.8 smd: SH2(-6.65,1.4) SH7(6.75,1.4)
  rect 2x1.8 smd: SH8(6.95,-0.9)
  silkscreen extent -6.95,-2 9.15,4.6, body extent -7.05,-1.45 6.75,4.25, height 2.8

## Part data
C1 C2 C5 C6 C8 C9 C16 C17 C18 C19 C27 C28 C33 C34 C54 C55 C65 C66 C71 C72 C73: library part CAP_SMD_MLCC_0805, "CAP, MLCC"
C3 C4 C7 C10 C13 C14 C15 C20 C21 C22 C23 C24 C25 C26 C29 C32 C35 C38 C39 C40 C41 C42 C43 C44 C45 C46 C47 C48 C49 C50 C51 C52 C53 C56 C57 C58 C59 C60 C61 C62 C63 C64 C67 C68 C74 C75 C76: library part CAP_SMD_MLCC_0603, "CAP, MLCC"
C11 C12 C30 C31 C36 C37 C69 C70: library part CAP_SMD_MLCC_1206, "CAP, MLCC"
CR1 CR2 CR3 CR4 CR5: "Very low capacitance ESD protection", Manufacturer_Name=STMicroelectronics
D1 D2 D6 D8 D10: "4Line Bidirectional ESD Protection for High Speed Interfaces", Manufacturer_Name=onsemi, Manufacturer_Part_Number=ESD8104MUTAG
D3: library part LED_THD_5MM_RED, "LED, THD, 5MM, RED"
D4: "Schottky Diode 60V 5A SMA"
D5 D7 D9 D11: library part LED_THD_5MM_GRN, "LED, THD, 5MM, GREEN"
F1: library part FUSE_2A_2410, "Fuse, 2A, 125VDC, 2410, SMD, Fast Acting"
J1: library part CONN_PWR_JACKR2, "CONN, PWR JACK DC, PLUG DIAM 2.0MM RA THD"
L1: library part IND_TMPC0603H-8R2MG-D, "SMD Power Choke Coil 8.2uH 7.5A 7.3x6.6mm"
L2: "SMD Inductor 4.7uH 6.2A 6530", Manufacturer_Name=TDK
M1 M2 M3 M4: library part SCMH_M3, "SCREW mouting, M3, 3.0mm diameter and 6.0mm PanHead"
PUSB1: library part CONN_USB3_MICRO_B, "CONN, USB3, MICRO B, SMD"
PUSB2 PUSB3 PUSB4 PUSB5: library part CONN_USB3_A_USB1075, "CONN, USB3, A type, R/A, THD"
R1 R2 R3 R4 R5 R6 R7 R8 R9 R10 R11 R12 R13 R14 R15 R16 R17 R18 R19 R20 R21 R22 R23 R24 R25 R26 R27 R28 R29 R30 R31 R32 R33 R34 R35 R36 R37 R38 R39 R40 R41: library part RES_SMD_0603, "RESISTOR, SMD"
SW1: library part SWPBT_SPST_R_6X6_G, "SWITCH, PUSH BUTTON, TACTILE, THD, SPST, RIGHT"
U1 U3 U4 U6: "1A loading, 4.5-5.5V, 96mÎ© USB power switch, active-high, output discharge, reverse blocking 5-SOT-23 -40 to 125", Manufacturer_Name="Texas Instruments"
U2: "4.5V to 60 V input, 5 A step-down converter with Eco-Mode 8-SO PowerPAD 0 to 0", Manufacturer_Name="Texas Instruments"
U5: "Applications Function:USB Hub USB Protocol:USB 3.1；USB 2.0 Number of Channels:4 Voltage - Supply:3V~3.6V；1V~1.2V Voltage - Supply:3V~3.6V；1V~1.2V Data Rate:5Gbps Operating Temperature:0℃~+70℃ Operating Temperature:0℃~+70℃ Current - Supply:- Quiescent Supp", Current - Supply=-, JLCPCB Part Class="Extended Part", LCSC Part Name="VL817 USB 3.1 Gen1 Hub 控制器", Manufacturer="VIA Labs(威锋电子)", Operating Temperature=0℃~+70℃, Voltage - Supply=3V~3.6V；1V~1.2V
X1: "25MHz 12pF ±30ppm SMD5032-4P Crystals", Manufacturer_Name=TXC

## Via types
v1: diameter 0.5, hole 0.3, Top Layer to Bottom Layer, tented both sides, 628 vias
v2: diameter 0.7, hole 0.4, Top Layer to Bottom Layer, tented both sides, 40 vias
v3: diameter 0.8, hole 0.5, Top Layer to Bottom Layer, 32 vias

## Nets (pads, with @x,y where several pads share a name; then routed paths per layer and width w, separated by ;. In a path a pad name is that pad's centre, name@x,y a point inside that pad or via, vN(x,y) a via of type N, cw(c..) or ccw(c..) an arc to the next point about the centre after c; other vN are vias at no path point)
1.1V: C38.2 C43.2 C45.2 C47.2 C50.2 C52.2 C53.2 C61.2 C63.2 C72.1 C73.1 L2.2 U5.3 U5.9 U5.12 U5.22 U5.40 U5.46 U5.49 U5.61 U5.67 U5.70 U5.76 | length 70.6
  Top Layer w0.2: U5.12@45.601,34.2 v1@46.4,34.2 ; U5.9@45.601,35.399 46.126,35.399 v1(46.42,35.104) ; U5.3@45.601,37.799 v1(46.5,37.8) ; U5.76@46.401,39.399 46.401,38.601 46.482,38.52 46.482,37.818 v1(46.5,37.8) ; U5.22@47.201,30.601 47.201,31.052 47.6,31.45 v1(47.6,31.5) ; v1(48.8,38.7) 48.801,38.701 U5.70@48.801,39.399 ; v1(50,38.7) U5.67@50,39.399 ; v1(52.4,38.7) U5.61@52.4,39.399 ; v1(53.7,35.4) v1(53.7,35.4) U5.49@54.399,35.399 ; v1@53.7,34.2 U5.46@54.399,34.2 ; U5.40@54.399,31.8 56.5,31.8 60.8,27.5 64.8,27.5 65.3,27 C72.1@65.3,25.5
  Bottom Layer w0.2: v1(46.4,34.2) 46.439,34.161 46.739,34.161 C52.2@47.2,33.7 ; v1(46.42,35.104) 46.422,35.102 47.198,35.102 C38.2@47.2,35.1 ; v1(48.8,38.7) 48.8,38.65 49.6,37.85 C63.2@49.6,37.8 ; v1(50,38.7) 50,38.65 50.8,37.85 C47.2@50.8,37.8 ; C45.2@52,37.8 52,37.854 52.4,38.254 v1(52.4,38.7) ; 52.8,34.1 52.9,34.2 v1(53.7,34.2) ; C43.2@52.8,34.7 52.8,35.4 v1(53.7,35.4)
  Bottom Layer w0.4: v1(46.5,37.8) 47.2,37.8 ; v1@47.6,31.527 47.6,32.1 C50.2@47.2,32.5 47.35,32.65 47.2,32.8 C52.2@47.2,33.7 C38.2@47.2,35.1 47.2,37.8 ; v2@65.307,22.4 54.1,22.4 52.8,23.7 C53.2@52.8,33.5 52.8,34.1 C43.2@52.8,34.7 52.8,37 C45.2@52,37.8 C47.2@50.8,37.8 C63.2@49.6,37.8 C61.2@48.4,37.8 47.2,37.8
  other v2: 65.1,22.4 65.1,23.3
3.3V: C41.2 C42.2 C51.2 C54.2 C56.2 C59.2 C60.2 C62.2 C68.2 R36.1 U5.6 U5.15 U5.21 U5.29 U5.43 U5.52 U5.58 U5.64 U5.73 | length 41.4
  Top Layer w0.2: U5.15@45.601,32.999 46.399,32.999 v1(46.4,33) ; U5.6@45.601,36.598 46.498,36.598 v1(46.5,36.6) ; U5.21@46.8,30.601 v1(46.8,31.4) ; v1(47.6,38.7) U5.73@47.6,39.399 ; U5.29@50,30.601 v1(50,31.37) ; v1(51.2,38.7) 51.201,38.701 U5.64@51.201,39.399 ; v1(53.569,38.6) 53.599,38.63 U5.58@53.599,39.399 ; v1(53.6,36.6) 53.602,36.598 U5.52@54.399,36.598 ; v1(53.7,33) v1(53.7,33) U5.43@54.399,32.999
  Bottom Layer w0.2: C59.2@45.6,33 v1(46.4,33) ; C68.2@45.6,36.6 v1(46.5,36.6) ; v1(47.6,38.7) C51.2@47.6,39.4 ; C41.2@50,30.6 v1(50,31.37) ; v1(51.2,38.7) C56.2@51.2,39.4 ; v1(53.569,38.6) 53.585,38.615 53.585,39.385 C60.2@53.6,39.4 ; v1(53.6,36.6) C62.2@54.4,36.6 ; v1(53.7,33) C42.2@54.4,33
  Bottom Layer w0.4: v1(46.8,31.4) C54.2@46.8,30.6 ; C41.2@50,30.6 R36.1@48,30.6 C54.2@46.8,30.6 ; C42.2@54.4,33 C62.2@54.4,36.6 54.4,38.6 C60.2@53.6,39.4 C56.2@51.2,39.4 C51.2@47.6,39.4 46.1,39.4 45.6,38.9 C68.2@45.6,36.6 C59.2@45.6,33 45.6,30.934 45.934,30.6 C54.2@46.8,30.6
5V: C4.2 C16.2 C17.2 C18.2 C19.2 C26.2 C32.2 C55.2 C64.2 C71.1 D3.1 D4.2 L1.2 R1.1 R3.1 R8.2 R15.1 R16.1 R19.1 R20.1 R32.1 R33.1 R38.1 U1.5 U3.5 U4.5 U5.20 U5.38 U6.5 | length 119.7
  Top Layer w0.3: R33.1@2.7,24.7 C64.2@4,24.7 ; U6.5@3.95,27.125 3.9,27.175 3.9,28.2 4.2,28.5 v1(5,28.5) ; R3.1@8.7,24.7 C4.2@10,24.7 ; U1.5@9.9,27.175 9.9,28.2 10.2,28.5 v1(11,28.5) ; R16.1@14.7,24.7 C26.2@16,24.7 ; U3.5@15.9,27.175 15.9,28.2 16.2,28.5 v1(17,28.5) ; R20.1@20.7,24.7 C32.2@22,24.7 ; U4.5@21.9,27.175 21.9,28.2 22.2,28.5 v1(23,28.5) ; C17.2@56.5,13.5 55.3,13.5 55,13.8 55,18.5 55.5,19 R8.2@68.3,19
  Top Layer w0.5: 43.5,13.7 43.5,27.1 44.4,28 C55.2@46,28 ; 51.2,13.9 51.3,14 R38.1@51.3,15.2 ; 52.734,13.534 53.1,13.9 53.1,27.1 C71.1@54,28 ; 55,13.8 55,8.7 56.2,7.5 87,7.5 92.23,12.73 D3.1@95,12.73
  Bottom Layer w0.3: R32.1@3.7,28.5 v1(5,28.5) ; R1.1@9.7,28.5 v1(11,28.5) ; R15.1@15.7,28.5 v1(17,28.5) ; R19.1@21.7,28.5 v1(23,28.5)
D0_N: CR1.3 PUSB1.2 | length 7.3
  Top Layer w0.2: v2(93.1,36.515) 93.217,36.515 93.467,36.765 94.416,36.765 95.331,36.765 95.496,36.6 PUSB1.2@96.05,36.6
  Bottom Layer w0.2: CR1.3@89.38,35.978 89.587,35.978 90.377,36.768 91.444,36.768 91.448,36.765 92.733,36.765 92.983,36.515 v2(93.1,36.515)
D0_P: CR1.1 PUSB1.3 | length 7.3
  Top Layer w0.2: v2(93.1,37.335) 93.217,37.335 93.467,37.085 94.549,37.085 95.331,37.085 95.496,37.25 PUSB1.3@96.05,37.25
  Bottom Layer w0.2: CR1.1@89.38,37.878 89.587,37.878 90.377,37.088 91.577,37.088 91.58,37.085 92.733,37.085 92.983,37.335 v2(93.1,37.335)
D1_N: CR2.6 PUSB2.2 | length 27.5
  Top Layer w0.2: CR2.6@28.05,59.362 28.201,59.513 28.201,60.001 28.84,60.64 28.84,70.093 30.767,72.02 38.133,72.02 39.737,70.416 39.737,67.54 PUSB2.2@40.577,66.7
D1_P: CR2.4 PUSB2.3 | length 26.4
  Top Layer w0.2: CR2.4@29.95,59.362 29.799,59.513 29.799,60.001 29.5,60.3 29.16,60.64 29.16,69.96 30.9,71.7 38,71.7 39.417,70.283 39.417,67.54 PUSB2.3@38.577,66.7
D2_N: CR3.6 PUSB3.2 | length 27.7
  Top Layer w0.2: CR3.6@49.05,59.3 49.201,59.451 49.201,59.938 49.84,60.578 49.84,70.293 51.567,72.02 59.18,72.02 60.713,70.487 60.713,67.54 PUSB3.2@61.553,66.7
D2_P: CR3.4 PUSB3.3 | length 26.6
  Top Layer w0.2: CR3.4@50.95,59.3 50.799,59.451 50.799,59.938 50.5,60.238 50.16,60.578 50.16,70.16 51.7,71.7 59.047,71.7 60.393,70.354 60.393,67.54 PUSB3.3@59.553,66.7
D3_N: CR4.6 PUSB4.2 | length 27.8
  Top Layer w0.2: CR4.6@70.05,59.362 70.201,59.513 70.201,60.001 70.84,60.64 70.84,70.393 72.467,72.02 80.333,72.02 81.69,70.663 81.69,67.54 PUSB4.2@82.53,66.7
D3_P: CR4.4 PUSB4.3 | length 26.7
  Top Layer w0.2: CR4.4@71.95,59.362 71.799,59.513 71.799,60.001 71.5,60.3 71.16,60.64 71.16,70.26 72.6,71.7 80.2,71.7 81.37,70.53 81.37,67.54 PUSB4.3@80.53,66.7
D4_N: CR5.6 PUSB5.2 | length 27.5
  Top Layer w0.2: CR5.6@7.05,59.362 7.201,59.513 7.201,60.001 7.84,60.64 7.84,69.893 9.967,72.02 17.28,72.02 18.76,70.54 18.76,67.54 PUSB5.2@19.6,66.7
D4_P: CR5.4 PUSB5.3 | length 26.4
  Top Layer w0.2: CR5.4@8.95,59.362 8.799,59.513 8.799,60.001 8.5,60.3 8.16,60.64 8.16,69.76 10.1,71.7 17.147,71.7 18.44,70.407 18.44,67.54 PUSB5.3@17.6,66.7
